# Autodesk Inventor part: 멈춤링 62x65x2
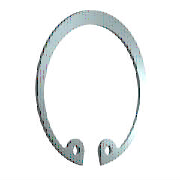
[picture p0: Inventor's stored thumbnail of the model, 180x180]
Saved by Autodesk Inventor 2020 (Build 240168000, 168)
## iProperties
Created: 2012-02
Part Number: 멈춤링 62x65x2
Material: 강철, 연강
Description: 스프링 리테이닝 링
Document SubType Name: Modeling
Standard: JIS B 2804
Designer: mdu
Standards Organization: JIS
Language: ko-KR
Size Designation: 62x2
Categories: <MemberInstance><Categories><Category DisplayName="샤프트 부품" InternalName="7f7aeb1f-a693-4053-b835-cee3144e0d98" Mnemonic="SHFT"><Category DisplayName="써클립" Inter
Density: 1 g/cm^3
Appearance: 강철
IsCustomPart: 1
Author: mdu
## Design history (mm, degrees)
sketch "스케치1"
  geometry: L1 (0, 15.113)-(0, -73.177) reference; L2 (-45.5, 0)-(45.5, 0) reference; L3 (-4.964, 1.5)-(1.502, 1.5); L4 (0, -4)-(-5.307, -4); L5 (0, -31)-(-13.368, -60.623); L6 (-13.368, -60.623)-(-26.939, -54.499); L7 (-11.949, -57.479)-(-22.5, -52.717); L8 (-9.671, -58.507)-(-11.05, -61.564); L9 (9.671, -58.507)-(11.05, -61.564); C1 r 1.25 at (-11.949, -57.479); C2 r 1.25 at (11.949, -57.479); A1 r 28.375 centre (0, -32.375) between (16.406, -55.527) and (-16.406, -55.527); A2 r 32.5 centre (0, -31) between (11.05, -61.564) and (-11.05, -61.564); A3 r 2.5 centre (-11.949, -57.479) between (-9.671, -58.507) and (-13.455, -55.483); A4 r 2.5 centre (-14.96, -53.487) between (-16.406, -55.527) and (-13.455, -55.483); A5 r 2.5 centre (14.96, -53.487) between (13.455, -55.483) and (16.406, -55.527); A6 r 2.5 centre (11.949, -57.479) between (13.455, -55.483) and (9.671, -58.507); 3 further points
  constraints: 15 point on circle, 14 end point, 9 symmetric about line, 8 centre point, 6 tangent, 4 coincident, 4 point on line, 3 perpendicular, 1 parallel, 4 other
  dimensions: "d8" = 1.375 distance of A1.centre L5.start (= 0.25 x SRB1); "d38" = 5.5 distance between parallel lines of L4 L3 (= SRB1); "d39" = 31 distance from line of L5.start L2 (= 0.5 x WD); "d43" = 32.5 radius of A2 (= 0.5 x ND); "d45" = 3.45 distance between parallel lines of L7 L6 (= 0.5 x SRB2); "d46" = 2.5 radius of A4 (= SD5); "d47" = 11.05 distance from line of L1 L8.end (= 0.17 x ND); "d48" = 2.5 diameter of C1 (= SD5); "d49" = 2.5 radius of A3 (= SD5)
extrude "본체" new body sketch "스케치1" distance "d2" = 2 (= SD); taper "d3" = 0 deg
workaxis "Work Axis1"
workaxis "Work Axis2"
workplane "Work Plane1"
node "작업 평면2"
body "Solid1"
other parameters: "WD" = 62 [user parameter; used in 1 equation term], "SD" = 2 [user parameter; used in 1 equation term], "SRB1" = 5.5 [user parameter; used in 2 equation terms], "ND" = 65 [user parameter; used in 2 equation terms], "SRB2" = 6.9 [user parameter; used in 1 equation term], "SD5" = 2.5 [user parameter; used in 3 equation terms], "d50" = 0, "d51" = 0, "d52" = 0, "d53" = 0, "SD6" = 66.2 [user parameter], "WDMAX" = 62 (= NND) [user parameter], "NND" = 62 [user parameter; used in 1 equation term]
